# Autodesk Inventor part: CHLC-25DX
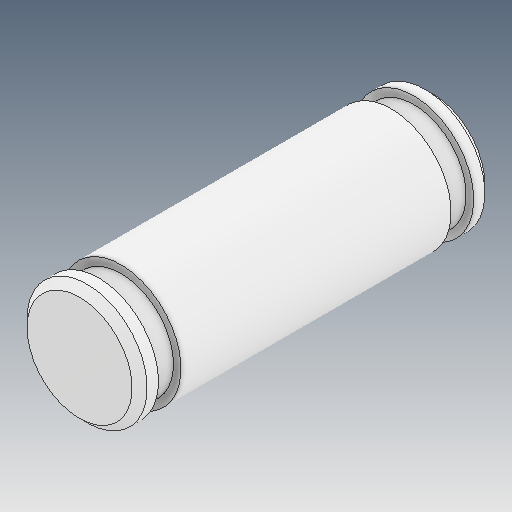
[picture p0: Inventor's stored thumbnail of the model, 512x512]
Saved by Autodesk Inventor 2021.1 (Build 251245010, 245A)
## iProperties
Created: 2021-05
Part Number: CHLC-25DX
Material: Ogólny
Document SubType Name: Modeling
Designer: user
Density: 1 g/cm^3
Appearance: Domyślna
Author: user
Revision Number: ÈÎºÎ
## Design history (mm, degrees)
feature "ÊäÈë1"
node "Bryła1"
